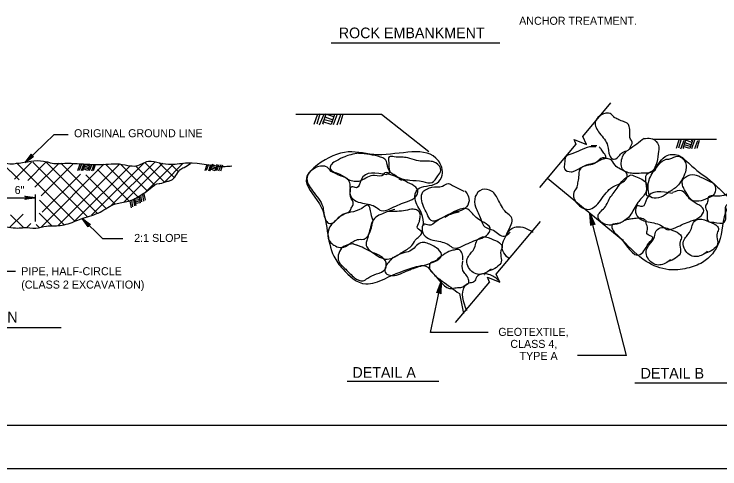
# Model space of a CAD drawing. Extents: x 5 to 910, y -47 to 547.
# Drawn here: x 364.1 to 606.1, y -46.5 to 109.5 of the extents above; entities that cross this region are included whole.
import ezdxf

# ---------------------------------------------------------------- set-up
doc = ezdxf.new("R2010")
doc.units = 0
for name, color, linetype in [('1', 7, 'Continuous'), ('2', 7, 'Continuous'), ('3', 7, 'Continuous'), ('PLT-BNDY', 7, 'Continuous')]:
    doc.layers.add(name, color=color, linetype=linetype)

msp = doc.modelspace()

# ---------------------------------------------------------------- linework, layer by layer
at = {"layer": '1'}
for p, q in [((490.06, 75.08), (460.61, 75.08)), ((468.07, 75.21), (466.86, 71.58)), ((468.89, 75.28), (467.89, 71.74)), ((470.98, 75.21), (469.79, 71.67)), ((473.72, 74.23), (470.93, 75.21)), ((474.8, 75.17), (473.47, 71.53)), ((476.83, 75.05), (475.76, 71.6)), ((470.24, 75.01), (468.71, 71.37)), ((473.08, 72.56), (470.34, 73.2)), ((473.52, 73.11), (470.77, 74.12)), ((473.88, 75.01), (472.76, 71.65)), ((473.93, 74.89), (473.4, 75.01)), ((475.99, 74.89), (474.77, 71.44)), ((470.18, 71.67), (469.92, 71.9)), ((472.76, 71.65), (469.97, 72.49)), ((604.92, 66.47), (583.12, 66.47)), ((592, 66.24), (591.01, 63.33)), ((592.66, 66.28), (591.84, 63.45)), ((593.74, 66.08), (592.5, 63.15)), ((594.31, 66.24), (593.37, 63.4)), ((596.34, 64.55), (594.15, 65.35)), ((596.5, 65.44), (594.28, 66.24)), ((596.64, 66.08), (595.75, 63.38)), ((596.69, 65.99), (596.25, 66.08)), ((597.37, 66.19), (596.32, 63.29)), ((598.33, 65.99), (597.35, 63.22)), ((599, 66.1), (598.15, 63.33)), ((593.67, 63.4), (593.48, 63.59)), ((595.75, 63.38), (593.51, 64.07)), ((596, 64.11), (593.8, 64.61)), ((386.59, 57.98), (385.85, 55.76)), ((387.16, 58.02), (386.4, 55.87)), ((387.89, 57.88), (387.07, 55.71)), ((388.39, 57.95), (387.55, 55.76)), ((387.8, 55.8), (387.64, 55.87)), ((389.36, 55.78), (387.78, 56.35)), ((389.68, 56.35), (387.94, 56.79)), ((389.88, 56.72), (388.21, 57.29)), ((390.02, 57.31), (388.37, 57.93)), ((390.11, 57.86), (389.36, 55.78)), ((390.13, 57.79), (389.84, 57.86)), ((390.68, 57.91), (389.86, 55.76)), ((391.39, 57.79), (390.61, 55.64)), ((391.89, 57.82), (391.21, 55.73)), ((430.17, 57.86), (429.42, 55.67)), ((430.74, 57.91), (429.96, 55.78)), ((431.45, 57.77), (430.7, 55.64)), ((431.98, 57.86), (431.15, 55.67)), ((431.41, 55.73), (431.22, 55.78)), ((432.96, 55.67), (431.41, 56.28)), ((433.26, 56.28), (431.52, 56.67)), ((433.47, 56.63), (431.77, 57.24)), ((433.63, 57.2), (431.98, 57.84)), ((433.69, 57.82), (432.96, 55.67)), ((433.72, 57.75), (433.44, 57.75)), ((434.29, 57.82), (433.47, 55.67)), ((435, 57.75), (434.2, 55.55)), ((435.5, 57.7), (434.82, 55.64)), ((407.15, 46.45), (405.37, 46.17)), ((405.37, 46.19), (405.78, 43.88)), ((406.97, 46.97), (406.7, 46.83)), ((406.93, 47.04), (407.34, 44.75)), ((407.43, 47.36), (407.77, 45.03)), ((408.05, 47.59), (408.44, 45.3)), ((408.5, 47.84), (408.96, 45.67)), ((403.81, 45.3), (404.23, 43.01)), ((404.27, 45.62), (404.68, 43.4)), ((404.96, 45.85), (405.37, 43.68)), ((407.29, 45.87), (405.51, 45.58)), ((407.29, 45.48), (405.58, 44.94)), ((407.34, 44.75), (405.67, 44.55)), ((405.94, 44), (405.78, 44.07)), ((526.63, 0.28), (506.81, 0.28)), ((574.01, -7.63), (557.29, -7.63))]:
    msp.add_line(p, q, dxfattribs=at)
msp.add_lwpolyline([(830.72, -31.53), (830.72, 532.47), (44.72, 532.47), (44.72, -31.53), (830.72, -31.53), (830.72, -5.17), (630.72, -5.17), (630.72, 59.51), (830.72, 59.51), (830.72, 88.47), (630.72, 88.47), (630.72, -31.53), (709.52, -31.53), (709.52, -5.17), (709.52, -31.53), (786.52, -31.53), (786.52, -5.17), (786.52, -17.48), (830.72, -17.48)], dxfattribs=at)
at = {"layer": '2'}
for p, q in [((530.63, 99.46), (472.82, 99.46)), ((506.21, 62.29), (490.06, 75.08)), ((367.87, 58.55), (377.82, 68.23)), ((377.82, 68.23), (382.61, 68.23)), ((360.21, 46.49), (371.3, 46.49)), ((371.3, 47.61), (371.3, 38.3)), ((574.01, -7.63), (561.48, 41.16)), ((387.36, 39.31), (394.41, 32.47)), ((394.41, 32.47), (401.39, 32.47)), ((354.1, 21.3), (364.53, 21.3)), ((506.81, 0.28), (510.6, 18.11)), ((380.25, 1.86), (302.46, 1.86)), ((509.64, -16.6), (478.28, -16.6)), ((608.7, -17.07), (576.87, -17.07))]:
    msp.add_line(p, q, dxfattribs=at)
msp.add_lwpolyline([(561.97, 37.18), (562.22, 37.4), (561.48, 41.16), (561.97, 37.18), (561.86, 36.93), (561.48, 41.16), (562.6, 37.48), (562.93, 37.43), (561.48, 41.16), (563.15, 37.27), (562.93, 37.43)], dxfattribs=at)
for points in [[(260.75, 58.3), (266.93, 58.3), (272.74, 57.24), (279.45, 57.59), (291.62, 57.06), (301.32, 55.67), (305.05, 56.53), (311.2, 56.9), (316.83, 57.43), (317.2, 57.79), (324.79, 57.95), (337.86, 56.53), (345.06, 57.24), (352.48, 57.79), (357.94, 59.01), (361.31, 58.3), (366.43, 58.48), (375.24, 58.85), (376.47, 58.48), (381.42, 58.3), (390.04, 57.95), (395.51, 57.95), (399.24, 58.14), (403.11, 57.59), (405.94, 57.43), (410.17, 59.01), (414.04, 58.48), (417.93, 57.95), (423.56, 58.48), (436.46, 57.24), (438.75, 57.43)], [(358.77, 36.42), (362.15, 36.42), (365.33, 36.08), (367.44, 36.26), (371.51, 36.08), (375.19, 36.79), (379.82, 36.97), (385.28, 38.55), (387.73, 39.44), (393.54, 41.55), (398.85, 44.39), (403.27, 45.28), (406.95, 47.02), (408.37, 47.91), (410.68, 49.67), (413.84, 51.43), (414.02, 51.43), (416.65, 52.14), (417.93, 52.49), (420.93, 56.01), (422.35, 56.9), (424.57, 58.18)]]:
    msp.add_spline(points, degree=3, dxfattribs=at)
at = {"layer": '3'}
for p, q in [((559.05, 67.5), (568.71, 79.01)), ((544.34, 49.95), (556.83, 64.87)), ((561.96, 64.39), (563.86, 64.36)), ((365.78, 52.63), (359.8, 58.62)), ((364.17, 52.83), (370, 58.64)), ((384.85, 38.44), (364.85, 58.43)), ((368.73, 52.41), (375.1, 58.82)), ((389.22, 39.99), (370.55, 58.66)), ((371.2, 50.07), (379.52, 58.36)), ((373.39, 47.11), (384.48, 58.18)), ((392.54, 41.18), (374.9, 58.82)), ((395.74, 42.72), (380.11, 58.34)), ((390.64, 40.5), (408.53, 58.39)), ((397.04, 43.43), (412.33, 58.71)), ((401.64, 44.96), (415.03, 58.34)), ((415.6, 51.84), (408.92, 58.53)), ((418.82, 53.51), (413.84, 58.5)), ((415.62, 51.87), (422.09, 58.34)), ((373.32, 36.42), (394.85, 57.95)), ((379.15, 36.97), (400.18, 58)), ((384.71, 38.32), (403.86, 57.47)), ((403.52, 45.32), (392.72, 56.15)), ((406.54, 46.83), (395.42, 57.95)), ((409.6, 48.94), (400.57, 57.95)), ((412.46, 50.65), (405.67, 57.45)), ((409.01, 48.34), (418.69, 58.02)), ((420.4, 55.41), (417.86, 57.95)), ((373.7, 41.5), (386.82, 54.59)), ((398.76, 44.34), (388.71, 54.38)), ((492.94, 55.36), (494.66, 54.26)), ((600.07, 53.34), (603.09, 51.83)), ((495.98, 52.98), (496.87, 52.5)), ((514.15, 50.83), (518.29, 48.74)), ((572.8, 31.85), (546.97, 53.11)), ((381.07, 37.34), (372.76, 45.65)), ((376.98, 36.86), (372.63, 41.21)), ((362.65, 36.39), (367.18, 40.91)), ((367.24, 36.25), (362.85, 40.65)), ((368.43, 36.24), (369.84, 37.64)), ((372.7, 36.26), (371.62, 37.34)), ((486.3, 35.75), (486.81, 37.21)), ((529.36, 20.28), (544.51, 38.31)), ((572.8, 32.15), (572.8, 31.85)), ((480.38, 30.65), (481.66, 30.26)), ((525.34, 20.01), (525.22, 20.01)), ((515.43, 3.72), (527.14, 17.65)), ((516.73, 13.6), (518.11, 6.83))]:
    msp.add_line(p, q, dxfattribs=at)
for points in [[(556.76, 64.8), (556.12, 66.47), (560.36, 64.73), (559.05, 67.5)], [(370.55, 60.56), (370.3, 60.65), (367.87, 58.55), (370.55, 60.56), (370.78, 60.58), (367.87, 58.55), (370.05, 60.88), (369.98, 61.13), (367.87, 58.55), (370, 61.38), (369.98, 61.13)], [(367.99, 46.9), (368.1, 46.67), (371.3, 46.49), (367.99, 46.9), (367.8, 47.06), (371.3, 46.49), (368.1, 46.33), (367.99, 46.1), (371.3, 46.49), (367.8, 45.94), (367.99, 46.1)], [(389.47, 36.7), (389.54, 36.95), (387.36, 39.31), (389.47, 36.7), (389.47, 36.47), (387.36, 39.31), (389.77, 37.2), (390.02, 37.29), (387.36, 39.31), (390.27, 37.27), (390.02, 37.29)], [(527.07, 17.56), (526.43, 19.25), (530.64, 17.49), (529.36, 20.28)], [(509.23, 13.99), (509.53, 14.07), (510.55, 17.78), (509.23, 13.99), (509.01, 13.83), (510.55, 17.78), (509.94, 13.99), (510.19, 13.8), (510.55, 17.78), (510.33, 13.55), (510.19, 13.8)]]:
    msp.add_lwpolyline(points, dxfattribs=at)
for points in [[(569.85, 74.11), (568.39, 75.34), (567.43, 75.5), (565.71, 75.07), (563.31, 72.46), (564.82, 68.66), (567.56, 64.41), (568.32, 60.89), (569.21, 59.88), (569.85, 59.72), (571.7, 61.09), (573.12, 62.26), (575, 63.1), (575.55, 64.2), (575.98, 65.1), (575.2, 67.11), (575.14, 68.05), (575.07, 70.52), (574.52, 71.84), (573.49, 72.46), (571.77, 73.06), (571.06, 73.42), (569.69, 74.04)], [(579.92, 66.74), (580.6, 66.83), (582.91, 66.65), (584.97, 64.52), (584.95, 61.57), (584.15, 57.64), (582.2, 55.21), (579.05, 54.87), (576.23, 54.82), (574.27, 55.21), (572.87, 56.01), (572.25, 57.84), (573.53, 61.92), (574.95, 63.1), (580.08, 66.93)], [(504.58, 36.94), (503.78, 41.1), (501.54, 46.07), (502.34, 49.27), (509.05, 51.49), (510.83, 54.21), (509.53, 59.18), (488.73, 61.26), (478.66, 62.2), (468.12, 57.74), (464.27, 53.23), (468.76, 44.44), (471.46, 35.02), (473.72, 26.39), (476.74, 22.07), (484.61, 16.94), (491.13, 18.7), (502.02, 22.87), (505.2, 23.03), (507.6, 20.65), (510.83, 17.9), (516.73, 13.6)], [(563.47, 63.84), (562.19, 64), (558.89, 63.08), (555.6, 61.64), (553.26, 60.57), (552.81, 58.28), (552.81, 56.45), (555.05, 55.39), (556.33, 55.71), (559.9, 57.48), (562.39, 58.05), (565.73, 59.67), (566.97, 60.36), (566.3, 61.78), (565.37, 63.13), (564.66, 63.91)], [(482.28, 61.81), (479.53, 61.26), (477.47, 60.55), (474.59, 59.18), (472.9, 57.92), (472.44, 56.68), (475.73, 54.56), (478.73, 52.77), (482.74, 52.31), (485.37, 53.69), (487.65, 54.19), (490.7, 54.44), (491.34, 55.2), (492.83, 55.06), (492.37, 56.55), (492.02, 57.92), (491.2, 59.75), (489.74, 60.46), (482.16, 61.72)], [(494.27, 54.6), (495.55, 53.64), (499.71, 52.52), (504.17, 52.04), (507.38, 51.72), (509.3, 53.96), (510.42, 55.88), (508.66, 58.44), (507.06, 58.93), (502.09, 59.25), (499.05, 60.18), (494.43, 60.53), (492.66, 60.53), (492.5, 58.6), (492.66, 56.52), (492.94, 55.24)], [(582.27, 46.93), (580.95, 47.36), (580.95, 48.55), (581.47, 54.96), (583.81, 55.97), (584.33, 57.13), (585.5, 58.83), (588.02, 61), (592.23, 60.84), (594.08, 59.51), (596.44, 57.32), (603.5, 51.76), (608.22, 47.36), (609.41, 46.06), (608.56, 43.02), (605.7, 31.05), (600.14, 24.33), (594.77, 22.31), (588.54, 21.81), (580.79, 24.65), (572.8, 31.85)], [(588.73, 48.76), (587.95, 47.98), (582.32, 46.79), (581.45, 49.4), (581.77, 52.47), (584.4, 56.97), (587.65, 59.67), (588.93, 59.83), (591.65, 60.75), (593.85, 59.33), (594.4, 56.01), (593.32, 53.22), (593.21, 53.02), (591.81, 50.86), (588.93, 48.62)], [(556.88, 49.86), (555.85, 47.71), (555.96, 46.49), (557.06, 44.57), (561, 42.51), (565.07, 45.53), (569.32, 50.22), (573.35, 52.31), (574.27, 53.7), (574.24, 54.53), (571.98, 56.31), (570.12, 57.68), (568.5, 59.65), (566.99, 59.97), (565.76, 60.18), (563.6, 58.6), (562.48, 58.21), (559.51, 57.32), (558.11, 56.26), (557.7, 54.78), (557.47, 52.53), (557.29, 51.6), (556.99, 49.72)], [(472.71, 55.63), (470.88, 57.19), (469.69, 57.35), (467.54, 56.82), (464.55, 53.55), (466.4, 48.84), (469.88, 43.51), (470.79, 39.11), (471.91, 37.81), (472.71, 37.65), (475.03, 39.36), (476.83, 40.83), (479.17, 41.88), (479.85, 43.23), (480.38, 44.35), (479.42, 46.87), (479.33, 48.04), (479.24, 51.15), (478.55, 52.79), (477.27, 53.55), (475.09, 54.33), (474.27, 54.78), (472.53, 55.54)], [(491.84, 54.37), (483.06, 52.63), (481.43, 49.91), (479.85, 50.23), (479.21, 47.99), (483.51, 44.63), (488.32, 43.18), (489.92, 42.06), (492.94, 42.7), (498.22, 44.97), (501.27, 46.36), (502.55, 48.47), (498.22, 52.13), (492.46, 54.56), (491.84, 54.69)], [(575.55, 54.39), (577.7, 53.59), (581.08, 50.91), (580.4, 47.91), (577.93, 44.85), (575.18, 40.32), (569.94, 37.27), (565.39, 38.14), (564.27, 40.09), (566.44, 43.02), (568.66, 46.88), (569.51, 47.94), (570.81, 49.79), (572.48, 52.03), (574.45, 53.75), (575.62, 54.39)], [(603.44, 51.87), (603.8, 51.44), (604.56, 49.77), (603.92, 47.46), (601.88, 46.29), (598.81, 45.31), (596.39, 45.67), (594.86, 47.71), (593.69, 49.63), (593.19, 51.19), (593.19, 52.44), (594.22, 53.59), (597.51, 54.39), (598.93, 53.84), (600.07, 53.34)], [(518.59, 48.86), (519.04, 48.31), (520.03, 46.23), (519.2, 43.34), (516.64, 41.88), (512.82, 40.65), (507.03, 38.72), (505.64, 40.99), (503.74, 46.07), (504.24, 48.47), (505.77, 49.57), (507.28, 50.12), (510.97, 50.51), (512.98, 51.33), (514.42, 50.69)], [(533.02, 34.22), (534.49, 37.28), (534.78, 39.5), (533.37, 40.94), (530.16, 45.56), (527.76, 48.77), (524.56, 49.27), (522.18, 46.87), (522.32, 43.34), (524.08, 39.18), (525.52, 36.48), (528.4, 35.34), (532.06, 33.26), (534.17, 34.72)], [(589.8, 47.94), (581.02, 46.2), (579.39, 43.47), (577.81, 43.77), (577.15, 41.55), (581.47, 38.19), (586.28, 36.75), (587.88, 35.63), (590.92, 36.27), (596.18, 38.51), (599.23, 39.93), (600.51, 42.03), (596.18, 45.69), (592.84, 48.9), (589.8, 48.26)], [(608.45, 47.73), (606.11, 47.02), (601.99, 46.49), (601.81, 45.05), (601.1, 43.61), (601.65, 41.67), (601.99, 38.44), (603.99, 38.08), (607.55, 38.08), (608.1, 40.75), (608.26, 43.8), (610.23, 46.31), (608.45, 47.36)], [(487.11, 38.93), (486.26, 41.97), (485.6, 43.89), (483.24, 42.84), (479.53, 41.51), (477.82, 41.08), (473.9, 38.29), (472.62, 36.98), (472.39, 31.36), (473.7, 30.26), (475.85, 29.41), (478.25, 30.08), (480.84, 31.79), (482.78, 32.23), (483.88, 32.23), (484.95, 32.89), (485.6, 33.74), (487.13, 38.88)], [(516.62, 41.54), (508.98, 38.47), (506.21, 37.08), (504.63, 37.4), (503.99, 35.15), (508.31, 31.81), (513.1, 30.35), (514.72, 29.25), (517.74, 29.89), (523, 32.13), (526.07, 33.55), (527.35, 35.63), (523, 39.32), (519.66, 42.52), (511.77, 39.73)], [(494.59, 42.48), (492.39, 41.79), (490.35, 41.01), (488.11, 39.78), (486.62, 37.65), (486.3, 36.44), (485.96, 35.22), (485.62, 33.94), (485, 31.79), (484.77, 30.51), (485.44, 28.95), (486.9, 27.74), (491.98, 25.41), (494.59, 26.21), (497.74, 28.18), (499.3, 29.14), (500.76, 30.51), (501.95, 32.29), (503.26, 33.51), (503.85, 34.65), (502.39, 36.02), (503.01, 38.31), (503.26, 39.68), (503.35, 40.83), (502.39, 42.11), (500.95, 42.54), (498.25, 42.11), (492.57, 41.79)], [(580.51, 38.78), (578.91, 39.49), (576.78, 39.31), (575, 39.13), (573.72, 38.78), (572.66, 38.26), (571.59, 37.71), (569.1, 37.18), (569.44, 35.22), (571.22, 33.41), (578.75, 26.98), (580.37, 28.76), (582.14, 31.44), (583.03, 32.88), (581.06, 34.12), (581.24, 35.56), (581.24, 36.45), (580.72, 38.26), (580.88, 38.78)], [(601.74, 28.12), (600.97, 27.46), (597.14, 26.34), (593.76, 29.22), (593.6, 31.62), (594.58, 33.23), (596.32, 35.95), (596.96, 38.01), (598.88, 39.13), (602.54, 38.17), (605.27, 36.59), (605.59, 35.95), (605.11, 34.35), (605.27, 31.78), (604.81, 29.7), (604.65, 29.54), (602.41, 27.94), (601.08, 27.48)], [(533.53, 25.75), (531.6, 28.31), (532.89, 33.74), (534.33, 35.66), (536.25, 36.48), (542.01, 34.72)], [(589.07, 25.26), (588.27, 24.6), (584.42, 23.46), (581.06, 26.36), (580.9, 28.76), (581.86, 30.34), (583.62, 33.07), (584.26, 35.15), (586.16, 36.27), (589.87, 35.28), (592.57, 33.71), (592.89, 33.07), (592.43, 31.49), (592.57, 28.9), (592.11, 26.84), (591.93, 26.66), (589.71, 25.08), (588.36, 24.62)], [(527.6, 22.04), (526.8, 21.38), (522.98, 20.24), (519.62, 23.12), (519.46, 25.52), (520.42, 27.12), (522.18, 29.85), (522.82, 31.91), (524.72, 33.03), (528.4, 32.09), (531.1, 30.49), (531.44, 29.85), (530.96, 28.25), (531.1, 25.68), (530.64, 23.6), (530.48, 23.44), (528.26, 21.84), (526.91, 21.38)], [(480.45, 30.65), (479.69, 30.58), (476.35, 29.16), (475.21, 26.74), (475.37, 24.68), (477.77, 21.93), (480.81, 19.05), (483.7, 17.95), (485.3, 18.91), (488.34, 20.35), (491.38, 22.11), (491.38, 24.81), (489.12, 26.74), (485.3, 28.5), (482.74, 29.8), (481.61, 30.26)], [(494.04, 26.05), (492.44, 24.31), (491.29, 22.39), (491.48, 20.63), (493.69, 19.83), (499.14, 21.56), (504.1, 23.19), (507.12, 24.13), (510.65, 27.01), (508.91, 29.25), (505.2, 31.01), (503.94, 31.17), (500.26, 28.45), (498.02, 27.65), (495.46, 26.69), (493.85, 25.73)], [(517.97, 25.06), (517.9, 26.46), (517.19, 28.18), (516.5, 28.7), (515.29, 28.61), (513.76, 28.27), (511.33, 26.96), (509.37, 25.5), (508.25, 24.65), (507.03, 24.31), (506.53, 23.37), (506.62, 21.82), (507.72, 20.51), (514.26, 15.34), (516.09, 15.71), (517.56, 15.8), (519.09, 16.71), (519.75, 17.08), (518.93, 20.19), (517.97, 21.54), (517.9, 24.74)], [(530.41, 17.95), (527.3, 20.03), (522.66, 19.23), (521.7, 17.63), (519.94, 17.15), (518.49, 16.03), (519.14, 7.79)]]:
    msp.add_spline(points, degree=3, dxfattribs=at)
at = {"layer": 'PLT-BNDY'}
msp.add_lwpolyline([(4.72, 547.47), (845.72, 547.47), (845.72, -46.53), (4.72, -46.53)], close=True, dxfattribs=at)

# ---------------------------------------------------------------- texts
at = {"layer": '2'}
for s, height, p in [('GEOTEXTILE,', 2.7454, (530.08, -0.9)), ('CLASS 4, ', 2.745, (534.2, -5.02)), ('TYPE A', 2.745, (537.37, -9.14))]:
    msp.add_text(s, height=height, dxfattribs=at).set_placement(p)
at = {"layer": '3'}
for s, height, p in [('ANCHOR TREATMENT.', 2.7454, (537.23, 105.82)), ('ROCK EMBANKMENT', 3.6603, (475.38, 101.2)), ('ORIGINAL GROUND LINE', 2.7454, (384.62, 67.24)), ('6"', 2.745, (364.26, 47.77)), ('2:1 SLOPE', 2.745, (405.25, 31.33)), ('PIPE, HALF-CIRCLE', 2.7454, (366.52, 19.91)), ('(CLASS 2 EXCAVATION)', 2.7454, (366.52, 15.33)), ('TYPICAL CROSS SECTION', 3.6603, (303, 3.69)), ('DETAIL A', 3.66, (480.06, -15.27)), ('DETAIL B', 3.66, (578.88, -15.54))]:
    msp.add_text(s, height=height, dxfattribs=at).set_placement(p)

doc.saveas('drawing.dxf')
